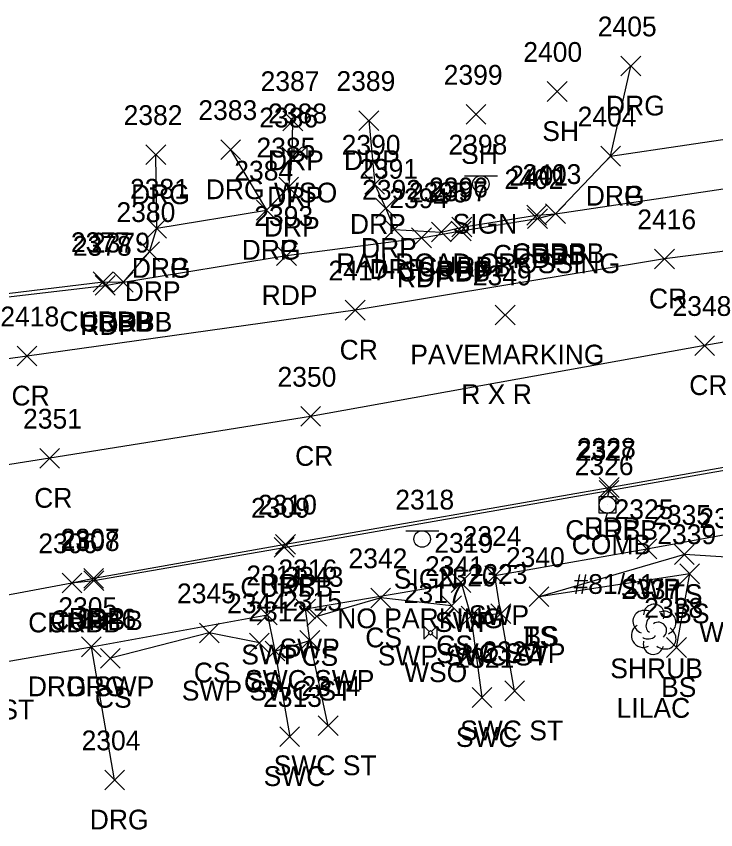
# Model space of a CAD drawing. Extents: x 1769141 to 1770817, y 735471 to 742405.
# Drawn here: x 1770321.5 to 1770392.1, y 741100 to 741182.2 of the extents above; entities that cross this region are included whole.
import ezdxf

# ---------------------------------------------------------------- set-up
doc = ezdxf.new("R2010")
doc.units = 0
for name, color, linetype in [('L_A', 7, 'Continuous'), ('L_C', 7, 'Continuous'), ('L_I', 7, 'Continuous'), ('L_TIC', 7, 'Continuous'), ('LELB', 7, 'Continuous'), ('LSH', 7, 'Continuous'), ('P_A', 7, 'Continuous'), ('P_I', 7, 'Continuous'), ('P_TIC', 7, 'Continuous'), ('PET', 7, 'Continuous'), ('PRC', 7, 'Continuous'), ('R_A', 7, 'Continuous'), ('R_C', 7, 'Continuous'), ('R_I', 7, 'Continuous'), ('R_TIC', 7, 'Continuous'), ('RC', 7, 'Continuous'), ('RDG', 7, 'Continuous'), ('RDP', 7, 'Continuous'), ('RSW', 7, 'Continuous'), ('S_A', 7, 'Continuous'), ('S_C', 7, 'Continuous'), ('S_I', 7, 'Continuous'), ('S_TIC', 7, 'Continuous'), ('SSGN', 7, 'Continuous'), ('U_A', 7, 'Continuous'), ('U_C', 7, 'Continuous'), ('U_I', 7, 'Continuous'), ('UP', 7, 'Continuous'), ('UWV', 7, 'Continuous')]:
    doc.layers.add(name, color=color, linetype=linetype)

msp = doc.modelspace()

# ---------------------------------------------------------------- linework, layer by layer
at = {"layer": 'L_TIC'}
for points in [[(1770375.124, 741173.581), (1770377.124, 741175.581)], [(1770377.124, 741173.581), (1770375.124, 741175.581)], [(1770366.927, 741171.269), (1770368.927, 741173.269)], [(1770368.927, 741171.269), (1770366.927, 741173.269)], [(1770387.976, 741126.777), (1770389.976, 741128.777)], [(1770389.976, 741126.777), (1770387.976, 741128.777)], [(1770388.51, 741124.825), (1770390.51, 741126.825)], [(1770390.51, 741124.825), (1770388.51, 741126.825)], [(1770357.296, 741122.393), (1770359.296, 741124.393)], [(1770359.296, 741122.393), (1770357.296, 741124.393)], [(1770373.288, 741122.515), (1770375.288, 741124.515)], [(1770375.288, 741122.515), (1770373.288, 741124.515)], [(1770373.288, 741122.515), (1770375.288, 741124.515)], [(1770375.288, 741122.515), (1770373.288, 741124.515)], [(1770364.462, 741121.596), (1770366.462, 741123.596)], [(1770366.462, 741121.596), (1770364.462, 741123.596)], [(1770350.84, 741120.521), (1770352.84, 741122.521)], [(1770352.84, 741120.521), (1770350.84, 741122.521)], [(1770339.971, 741118.85), (1770341.971, 741120.85)], [(1770341.971, 741118.85), (1770339.971, 741120.85)], [(1770345.036, 741117.84), (1770347.036, 741119.84)], [(1770347.036, 741117.84), (1770345.036, 741119.84)], [(1770387.178, 741117.38), (1770389.178, 741119.38)], [(1770389.178, 741117.38), (1770387.178, 741119.38)], [(1770329.979, 741116.292), (1770331.979, 741118.292)], [(1770331.979, 741116.292), (1770329.979, 741118.292)]]:
    msp.add_lwpolyline(points, dxfattribs=at)
at = {"layer": 'LELB'}
for points in [[(1770397.71, 741120.075), (1770393.749, 741127.462), (1770388.976, 741127.777), (1770374.288, 741123.515)], [(1770388.178, 741118.38), (1770389.51, 741125.825), (1770374.288, 741123.515)], [(1770365.462, 741122.596), (1770358.296, 741123.393), (1770351.84, 741121.521)], [(1770346.036, 741118.84), (1770340.971, 741119.85), (1770330.979, 741117.292)]]:
    msp.add_lwpolyline(points, dxfattribs=at)
at = {"layer": 'LSH'}
msp.add_line((1770385.857, 741120.272), (1770385.857, 741120.272), dxfattribs=at)
msp.add_line((1770385.857, 741120.272), (1770385.857, 741120.272), dxfattribs=at)
msp.add_arc((1770385.903, 741121.706), 1.047, 335.52715, 180.95627, dxfattribs=at)
for centre, major_axis, ratio, start_param, end_param in [((1770385.065, 741120.939), (1.21, -0.512), 0.895232, 1.570796, 4.712389), ((1770385.648, 741120.73), (-0.208, -0.792), 0.645439, 3.141593, 6.283185), ((1770386.898, 741120.856), (-1.141, -0.483), 0.949671, 1.570796, 4.712389), ((1770386.357, 741120.105), (-0.5, 0.667), 0.989748, 3.141593, 6.283185), ((1770384.773, 741119.564), (0.584, -1.042), 0.959034, 3.141593, 6.283185), ((1770386.857, 741119.439), (-1.09, 0.792), 0.841452, 1.570796, 4.712389), ((1770385.857, 741118.772), (0.265, 1.061), 0.942809, 1.570796, 4.712389), ((1770385.398, 741119.522), (-0.625, -0.083), 0.423636, 0, 3.141593)]:
    msp.add_ellipse(centre, major_axis=major_axis, ratio=ratio, start_param=start_param, end_param=end_param, dxfattribs=at)
at = {"layer": 'P_TIC'}
for points in [[(1770373.133, 741160.731), (1770375.133, 741162.731)], [(1770375.133, 741160.731), (1770373.133, 741162.731)], [(1770374.956, 741161.233), (1770376.956, 741163.233)], [(1770376.956, 741161.233), (1770374.956, 741163.233)], [(1770365.418, 741159.492), (1770367.418, 741161.492)], [(1770367.418, 741159.492), (1770365.418, 741161.492)], [(1770361.422, 741158.793), (1770363.422, 741160.793)], [(1770363.422, 741158.793), (1770361.422, 741160.793)], [(1770347.778, 741156.994), (1770349.778, 741158.994)], [(1770349.778, 741156.994), (1770347.778, 741158.994)], [(1770385.961, 741156.659), (1770387.961, 741158.659)], [(1770387.961, 741156.659), (1770385.961, 741158.659)], [(1770331.291, 741154.308), (1770333.291, 741156.308)], [(1770333.291, 741154.308), (1770331.291, 741156.308)], [(1770329.449, 741153.982), (1770331.449, 741155.982)], [(1770331.449, 741153.982), (1770329.449, 741155.982)], [(1770354.709, 741151.482), (1770356.709, 741153.482)], [(1770356.709, 741151.482), (1770354.709, 741153.482)], [(1770390.031, 741147.9), (1770392.031, 741149.9)], [(1770392.031, 741147.9), (1770390.031, 741149.9)], [(1770321.559, 741146.84), (1770323.559, 741148.84)], [(1770323.559, 741146.84), (1770321.559, 741148.84)], [(1770350.212, 741140.744), (1770352.212, 741142.744)], [(1770352.212, 741140.744), (1770350.212, 741142.744)], [(1770323.852, 741136.505), (1770325.852, 741138.505)], [(1770325.852, 741136.505), (1770323.852, 741138.505)], [(1770380.373, 741133.55), (1770382.373, 741135.55)], [(1770382.373, 741133.55), (1770380.373, 741135.55)], [(1770347.677, 741127.817), (1770349.677, 741129.817)], [(1770349.677, 741127.817), (1770347.677, 741129.817)], [(1770326.096, 741123.908), (1770328.096, 741125.908)], [(1770328.096, 741123.908), (1770326.096, 741125.908)], [(1770328.296, 741124.38), (1770330.296, 741126.38)], [(1770330.296, 741124.38), (1770328.296, 741126.38)]]:
    msp.add_lwpolyline(points, dxfattribs=at)
at = {"layer": 'PET'}
for points in [[(1770275.19, 741166.437), (1770275.977, 741155.599), (1770278.489, 741153.762), (1770283.376, 741153.643), (1770290.834, 741150.945), (1770293.216, 741150.928), (1770301.387, 741151.584), (1770330.449, 741154.982), (1770332.291, 741155.308), (1770348.778, 741157.994), (1770362.422, 741159.793), (1770366.418, 741160.492), (1770374.133, 741161.731), (1770375.956, 741162.233), (1770400.806, 741165.909), (1770403.378, 741166.25), (1770419.604, 741168.76)], [(1770267.402, 741112.794), (1770270.791, 741114.659), (1770274.372, 741115.598), (1770279.067, 741116.593), (1770280.95, 741116.863), (1770285.981, 741117.808), (1770287.654, 741118.086), (1770313.467, 741122.626), (1770315.364, 741122.711), (1770327.096, 741124.908), (1770329.296, 741125.38), (1770348.677, 741128.817), (1770381.373, 741134.55), (1770423.899, 741142.105)]]:
    msp.add_lwpolyline(points, dxfattribs=at)
at = {"layer": 'PRC'}
for points in [[(1770420.662, 741161.961), (1770386.961, 741157.659), (1770355.709, 741152.482), (1770322.559, 741147.84), (1770294.064, 741143.832), (1770270.938, 741141.774), (1770254.424, 741140.369)], [(1770422.288, 741154.401), (1770391.031, 741148.9), (1770351.212, 741141.744), (1770324.852, 741137.505), (1770305.015, 741134.401), (1770279.252, 741130.869), (1770261.05, 741126.482)]]:
    msp.add_lwpolyline(points, dxfattribs=at)
at = {"layer": 'R_TIC'}
for points in [[(1770382.565, 741176.161), (1770384.565, 741178.161)], [(1770384.565, 741176.161), (1770382.565, 741178.161)], [(1770348.417, 741170.625), (1770350.417, 741172.625)], [(1770350.417, 741170.625), (1770348.417, 741172.625)], [(1770356.088, 741170.642), (1770358.088, 741172.642)], [(1770358.088, 741170.642), (1770356.088, 741172.642)], [(1770334.578, 741167.197), (1770336.578, 741169.197)], [(1770336.578, 741167.197), (1770334.578, 741169.197)], [(1770342.128, 741167.701), (1770344.128, 741169.701)], [(1770344.128, 741167.701), (1770342.128, 741169.701)], [(1770348.337, 741166.95), (1770350.337, 741168.95)], [(1770350.337, 741166.95), (1770348.337, 741168.95)], [(1770380.526, 741167.048), (1770382.526, 741169.048)], [(1770382.526, 741167.048), (1770380.526, 741169.048)], [(1770380.526, 741167.048), (1770382.526, 741169.048)], [(1770382.526, 741167.048), (1770380.526, 741169.048)], [(1770348.001, 741163.915), (1770350.001, 741165.915)], [(1770350.001, 741163.915), (1770348.001, 741165.915)], [(1770356.694, 741164.195), (1770358.694, 741166.195)], [(1770358.694, 741164.195), (1770356.694, 741166.195)], [(1770345.758, 741161.585), (1770347.758, 741163.585)], [(1770347.758, 741161.585), (1770345.758, 741163.585)], [(1770345.758, 741161.585), (1770347.758, 741163.585)], [(1770347.758, 741161.585), (1770345.758, 741163.585)], [(1770357.813, 741161.771), (1770359.813, 741163.771)], [(1770359.813, 741161.771), (1770357.813, 741163.771)], [(1770373.048, 741161.08), (1770375.048, 741163.08)], [(1770375.048, 741161.08), (1770373.048, 741163.08)], [(1770374.956, 741161.233), (1770376.956, 741163.233)], [(1770376.956, 741161.233), (1770374.956, 741163.233)], [(1770374.956, 741161.233), (1770376.956, 741163.233)], [(1770376.956, 741161.233), (1770374.956, 741163.233)], [(1770365.492, 741159.882), (1770367.492, 741161.882)], [(1770367.492, 741159.882), (1770365.492, 741161.882)], [(1770334.659, 741159.753), (1770336.659, 741161.753)], [(1770336.659, 741159.753), (1770334.659, 741161.753)], [(1770334.659, 741159.753), (1770336.659, 741161.753)], [(1770336.659, 741159.753), (1770334.659, 741161.753)], [(1770358.676, 741159.647), (1770360.676, 741161.647)], [(1770360.676, 741159.647), (1770358.676, 741161.647)], [(1770363.412, 741159.376), (1770365.412, 741161.376)], [(1770365.412, 741159.376), (1770363.412, 741161.376)], [(1770363.412, 741159.376), (1770365.412, 741161.376)], [(1770365.412, 741159.376), (1770363.412, 741161.376)], [(1770333.942, 741157.391), (1770335.942, 741159.391)], [(1770335.942, 741157.391), (1770333.942, 741159.391)], [(1770329.25, 741154.349), (1770331.25, 741156.349)], [(1770331.25, 741154.349), (1770329.25, 741156.349)], [(1770331.291, 741154.308), (1770333.291, 741156.308)], [(1770333.291, 741154.308), (1770331.291, 741156.308)], [(1770331.291, 741154.308), (1770333.291, 741156.308)], [(1770333.291, 741154.308), (1770331.291, 741156.308)], [(1770380.358, 741133.253), (1770382.358, 741135.253)], [(1770382.358, 741133.253), (1770380.358, 741135.253)], [(1770347.535, 741127.502), (1770349.535, 741129.502)], [(1770349.535, 741127.502), (1770347.535, 741129.502)], [(1770384.176, 741127.353), (1770386.176, 741129.353)], [(1770386.176, 741127.353), (1770384.176, 741129.353)], [(1770368.828, 741124.643), (1770370.828, 741126.643)], [(1770370.828, 741124.643), (1770368.828, 741126.643)], [(1770326.096, 741123.908), (1770328.096, 741125.908)], [(1770328.096, 741123.908), (1770326.096, 741125.908)], [(1770328.309, 741124.136), (1770330.309, 741126.136)], [(1770330.309, 741124.136), (1770328.309, 741126.136)], [(1770365.412, 741123.952), (1770367.412, 741125.952)], [(1770367.412, 741123.952), (1770365.412, 741125.952)], [(1770349.707, 741121.277), (1770351.707, 741123.277)], [(1770351.707, 741121.277), (1770349.707, 741123.277)], [(1770345.845, 741120.665), (1770347.845, 741122.665)], [(1770347.845, 741120.665), (1770345.845, 741122.665)], [(1770366.41, 741120.56), (1770368.41, 741122.56)], [(1770368.41, 741120.56), (1770366.41, 741122.56)], [(1770366.41, 741120.56), (1770368.41, 741122.56)], [(1770368.41, 741120.56), (1770366.41, 741122.56)], [(1770369.433, 741120.809), (1770371.433, 741122.809)], [(1770371.433, 741120.809), (1770369.433, 741122.809)], [(1770369.433, 741120.809), (1770371.433, 741122.809)], [(1770371.433, 741120.809), (1770369.433, 741122.809)], [(1770350.128, 741118.098), (1770352.128, 741120.098)], [(1770352.128, 741118.098), (1770350.128, 741120.098)], [(1770350.128, 741118.098), (1770352.128, 741120.098)], [(1770352.128, 741118.098), (1770350.128, 741120.098)], [(1770328.06, 741117.452), (1770330.06, 741119.452)], [(1770330.06, 741117.452), (1770328.06, 741119.452)], [(1770328.06, 741117.452), (1770330.06, 741119.452)], [(1770330.06, 741117.452), (1770328.06, 741119.452)], [(1770346.607, 741117.02), (1770348.607, 741119.02)], [(1770348.607, 741117.02), (1770346.607, 741119.02)], [(1770346.607, 741117.02), (1770348.607, 741119.02)], [(1770348.607, 741117.02), (1770346.607, 741119.02)], [(1770370.827, 741112.996), (1770372.827, 741114.996)], [(1770372.827, 741112.996), (1770370.827, 741114.996)], [(1770367.527, 741112.327), (1770369.527, 741114.327)], [(1770369.527, 741112.327), (1770367.527, 741114.327)], [(1770351.987, 741109.469), (1770353.987, 741111.469)], [(1770353.987, 741109.469), (1770351.987, 741111.469)], [(1770348.103, 741108.373), (1770350.103, 741110.373)], [(1770350.103, 741108.373), (1770348.103, 741110.373)], [(1770330.409, 741103.986), (1770332.409, 741105.986)], [(1770332.409, 741103.986), (1770330.409, 741105.986)]]:
    msp.add_lwpolyline(points, dxfattribs=at)
at = {"layer": 'RC'}
for points in [[(1770364.412, 741160.376), (1770366.492, 741160.882), (1770374.048, 741162.08), (1770375.956, 741162.233)], [(1770290.834, 741150.945), (1770293.288, 741151.247), (1770301.388, 741151.851), (1770330.25, 741155.349), (1770332.291, 741155.308)], [(1770327.096, 741124.908), (1770329.309, 741125.136), (1770348.535, 741128.502), (1770381.358, 741134.253), (1770424.024, 741141.766)]]:
    msp.add_lwpolyline(points, dxfattribs=at)
at = {"layer": 'RDG'}
for points in [[(1770381.526, 741168.048), (1770383.565, 741177.161)], [(1770343.128, 741168.701), (1770346.758, 741162.585)], [(1770335.659, 741160.753), (1770335.578, 741168.197)], [(1770331.409, 741104.986), (1770329.06, 741118.452)]]:
    msp.add_lwpolyline(points, dxfattribs=at)
at = {"layer": 'RDP'}
for points in [[(1770332.291, 741155.308), (1770334.942, 741158.391), (1770335.659, 741160.753), (1770346.758, 741162.585), (1770349.001, 741164.915), (1770349.337, 741167.95), (1770349.417, 741171.625)], [(1770357.088, 741171.642), (1770357.694, 741165.195), (1770358.813, 741162.771), (1770359.676, 741160.647), (1770364.412, 741160.376)], [(1770375.956, 741162.233), (1770381.526, 741168.048), (1770396.926, 741170.338), (1770398.792, 741167.297), (1770400.806, 741165.909)]]:
    msp.add_lwpolyline(points, dxfattribs=at)
at = {"layer": 'RSW'}
for points in [[(1770293.745, 741112.25), (1770315.627, 741116.109), (1770329.06, 741118.452), (1770346.845, 741121.665), (1770347.607, 741118.02), (1770351.128, 741119.098), (1770350.707, 741122.277), (1770366.412, 741124.952), (1770367.41, 741121.56), (1770370.433, 741121.809), (1770369.828, 741125.643), (1770385.176, 741128.353), (1770423.885, 741135.428)], [(1770367.41, 741121.56), (1770368.527, 741113.327)], [(1770371.827, 741113.996), (1770370.433, 741121.809)], [(1770352.987, 741110.469), (1770351.128, 741119.098)], [(1770347.607, 741118.02), (1770349.103, 741109.373)]]:
    msp.add_lwpolyline(points, dxfattribs=at)
at = {"layer": 'S_TIC'}
for points in [[(1770369.866, 741150.989), (1770371.866, 741152.989)], [(1770371.866, 741150.989), (1770369.866, 741152.989)]]:
    msp.add_lwpolyline(points, dxfattribs=at)
at = {"layer": 'SSGN'}
for p, q in [((1770366.769, 741166.068), (1770370.102, 741166.068)), ((1770368.416, 741165.235), (1770368.416, 741165.235)), ((1770360.831, 741130.179), (1770364.164, 741130.179)), ((1770362.478, 741129.346), (1770362.478, 741129.346))]:
    msp.add_line(p, q, dxfattribs=at)
for centre in [(1770368.416, 741165.235), (1770362.478, 741129.346)]:
    msp.add_circle(centre, 0.833, dxfattribs=at)
at = {"layer": 'UP'}
for p, q in [((1770381.455, 741134.464), (1770381.205, 741133.631)), ((1770380.372, 741131.964), (1770380.372, 741133.631)), ((1770380.372, 741133.631), (1770382.038, 741133.631)), ((1770382.038, 741133.631), (1770382.038, 741131.964)), ((1770381.205, 741132.797), (1770381.205, 741132.797)), ((1770382.038, 741131.964), (1770380.372, 741131.964)), ((1770380.955, 741131.131), (1770381.205, 741131.964))]:
    msp.add_line(p, q, dxfattribs=at)
msp.add_circle((1770381.205, 741132.797), 0.833, dxfattribs=at)
at = {"layer": 'UWV'}
for p, q in [((1770349.517, 741169.035), (1770350.066, 741168.486)), ((1770350.851, 741169.035), (1770350.302, 741168.486)), ((1770350.066, 741168.251), (1770349.517, 741167.702)), ((1770350.302, 741168.251), (1770350.851, 741167.702)), ((1770362.654, 741120.544), (1770363.203, 741119.995)), ((1770363.987, 741120.544), (1770363.439, 741119.995)), ((1770363.203, 741119.759), (1770362.654, 741119.211)), ((1770363.439, 741119.759), (1770363.987, 741119.211))]:
    msp.add_line(p, q, dxfattribs=at)
for points in [[(1770349.517, 741169.035), (1770349.517, 741167.702)], [(1770350.851, 741167.702), (1770350.851, 741169.035)], [(1770362.654, 741120.544), (1770362.654, 741119.211)], [(1770363.987, 741119.211), (1770363.987, 741120.544)]]:
    msp.add_lwpolyline(points, dxfattribs=at)
for points in [[(1770350.42, 741168.368), (1770350.184, 741168.604), (1770349.948, 741168.368), (1770350.184, 741168.133)], [(1770363.556, 741119.877), (1770363.321, 741120.113), (1770363.085, 741119.877), (1770363.321, 741119.642)]]:
    msp.add_lwpolyline(points, close=True, dxfattribs=at)

# ---------------------------------------------------------------- texts
at = {"layer": 'L_A'}
for s, p in [('SH', (1770374.613, 741169.581)), ('SH', (1770366.415, 741167.269)), ('TS', (1770387.386, 741122.777)), ('BS', (1770387.951, 741120.825)), ('CS', (1770356.737, 741118.393)), ('TS', (1770372.697, 741118.515)), ('BS', (1770372.729, 741118.515)), ('CS', (1770363.903, 741117.596)), ('CS', (1770350.281, 741116.521)), ('CS', (1770339.412, 741114.85)), ('SHRUB', (1770381.487, 741115.272)), ('CS', (1770344.477, 741113.84)), ('BS', (1770386.619, 741113.38)), ('CS', (1770329.42, 741112.292))]:
    msp.add_text(s, height=2, dxfattribs=at).set_placement(p)
at = {"layer": 'L_C'}
msp.add_text('LILAC', height=2, dxfattribs=at).set_placement((1770382.132, 741111.272))
at = {"layer": 'L_I'}
for s, p in [('2400', (1770372.699, 741177.581)), ('2399', (1770364.659, 741175.269)), ('2335', (1770385.717, 741130.777)), ('2334', (1770390.489, 741130.462)), ('2339', (1770386.242, 741128.825)), ('2342', (1770355.036, 741126.393)), ('2340', (1770370.942, 741126.515)), ('2340', (1770370.942, 741126.515)), ('2341', (1770362.769, 741125.596)), ('2343', (1770348.58, 741124.521)), ('2345', (1770337.711, 741122.85)), ('2337', (1770382.597, 741123.272)), ('2344', (1770342.776, 741121.84)), ('2338', (1770384.919, 741121.38)), ('2346', (1770327.664, 741120.292))]:
    msp.add_text(s, height=2, dxfattribs=at).set_placement(p)
at = {"layer": 'P_A'}
for s, p in [('RDP', (1770371.621, 741156.731)), ('RDP', (1770373.444, 741157.233)), ('RDP', (1770363.906, 741155.492)), ('RDP', (1770359.91, 741154.793)), ('RDP', (1770346.266, 741152.994)), ('CR', (1770385.394, 741152.659)), ('RDP', (1770327.937, 741149.982)), ('RDP', (1770329.779, 741150.308)), ('CR', (1770354.143, 741147.482)), ('CR', (1770389.464, 741143.9)), ('CR', (1770320.992, 741142.84)), ('CR', (1770349.645, 741136.744)), ('CR', (1770323.285, 741132.505)), ('RDP', (1770378.861, 741129.55)), ('RDP', (1770346.165, 741123.817)), ('RDP', (1770326.784, 741120.38)), ('RDP', (1770324.584, 741119.908))]:
    msp.add_text(s, height=2, dxfattribs=at).set_placement(p)
at = {"layer": 'P_I'}
for s, p in [('2402', (1770370.794, 741164.731)), ('2403', (1770372.617, 741165.233)), ('2397', (1770363.158, 741163.492)), ('2394', (1770359.163, 741162.793)), ('2393', (1770345.518, 741160.994)), ('2416', (1770384.213, 741160.659)), ('2379', (1770329.023, 741158.308)), ('2378', (1770327.189, 741157.982)), ('2417', (1770353.017, 741155.482)), ('2348', (1770387.771, 741151.9)), ('2418', (1770319.866, 741150.84)), ('2350', (1770347.866, 741144.744)), ('2351', (1770322.16, 741140.505)), ('2328', (1770378.113, 741137.55)), ('2310', (1770345.898, 741131.817)), ('2306', (1770323.702, 741127.908)), ('2307', (1770325.958, 741128.38))]:
    msp.add_text(s, height=2, dxfattribs=at).set_placement(p)
at = {"layer": 'R_A'}
for s, p in [('DRG', (1770381.053, 741172.161)), ('DRP', (1770346.905, 741166.625)), ('DRP', (1770354.576, 741166.642)), ('DRG', (1770333.066, 741163.197)), ('DRG', (1770340.616, 741163.701)), ('DRG', (1770379.014, 741163.048)), ('DRP', (1770346.825, 741162.95)), ('DRP', (1770379.014, 741163.048)), ('DRP', (1770346.489, 741159.915)), ('DRP', (1770355.182, 741160.195)), ('DRG', (1770344.246, 741157.585)), ('DRP', (1770344.246, 741157.585)), ('DRP', (1770356.301, 741157.771)), ('CURBB', (1770369.631, 741157.08)), ('CURBB', (1770371.539, 741157.233)), ('DRP', (1770373.444, 741157.233)), ('DRG', (1770333.147, 741155.753)), ('DRP', (1770333.147, 741155.753)), ('CURBB', (1770362.075, 741155.882)), ('DRP', (1770357.164, 741155.647)), ('CURBB', (1770359.994, 741155.376)), ('DRP', (1770361.9, 741155.376)), ('DRP', (1770332.43, 741153.391)), ('CURBB', (1770325.832, 741150.349)), ('CURBB', (1770327.874, 741150.308)), ('DRP', (1770329.779, 741150.308)), ('CURBB', (1770376.941, 741129.253)), ('CURBB', (1770344.117, 741123.502)), ('SWP', (1770382.539, 741123.353)), ('SWP', (1770367.19, 741120.643)), ('CURBB', (1770322.679, 741119.908)), ('CURBB', (1770324.892, 741120.136)), ('SWP', (1770363.775, 741119.952)), ('SWP', (1770348.069, 741117.277)), ('SWP', (1770344.207, 741116.665)), ('SWP SWC ST', (1770358, 741116.56)), ('SWP SWC ST', (1770358, 741116.56)), ('SWC SWP', (1770363.89, 741116.809)), ('SWC SWP', (1770363.89, 741116.809)), ('SWC SWP', (1770344.585, 741114.098)), ('SWC SWP', (1770344.585, 741114.098)), ('DRG SWP', (1770322.642, 741113.452)), ('DRG', (1770326.548, 741113.452)), ('SWP SWC ST', (1770338.197, 741113.02)), ('SWP SWC ST', (1770338.197, 741113.02)), ('SWP DRG ST', (1770306.344, 741111.109)), ('SWC ST', (1770366.323, 741108.996)), ('SWC', (1770365.89, 741108.327)), ('SWC ST', (1770347.483, 741105.469)), ('SWC', (1770346.465, 741104.373)), ('DRG', (1770328.897, 741099.986))]:
    msp.add_text(s, height=2, dxfattribs=at).set_placement(p)
at = {"layer": 'R_C'}
msp.add_text('WOODEN', height=2, dxfattribs=at).set_placement((1770390.467, 741118.944))
at = {"layer": 'R_I'}
for s, p in [('2405', (1770380.226, 741180.161)), ('2387', (1770346.158, 741174.625)), ('2389', (1770353.821, 741174.642)), ('2383', (1770339.868, 741171.701)), ('2382', (1770332.318, 741171.197)), ('2386', (1770346.022, 741170.95)), ('2404', (1770378.187, 741171.048)), ('2404', (1770378.187, 741171.048)), ('2390', (1770354.348, 741168.195)), ('2385', (1770345.741, 741167.915)), ('2384', (1770343.499, 741165.585)), ('2384', (1770343.499, 741165.585)), ('2391', (1770356.12, 741165.771)), ('2401', (1770371.277, 741165.08)), ('2403', (1770372.617, 741165.233)), ('2403', (1770372.617, 741165.233)), ('2396', (1770363.177, 741163.882)), ('2381', (1770332.966, 741163.753)), ('2381', (1770332.966, 741163.753)), ('2392', (1770356.416, 741163.647)), ('2395', (1770361.152, 741163.376)), ('2395', (1770361.152, 741163.376)), ('2380', (1770331.596, 741161.391)), ('2377', (1770326.99, 741158.349)), ('2379', (1770329.023, 741158.308)), ('2379', (1770329.023, 741158.308)), ('2327', (1770378.099, 741137.253)), ('2309', (1770345.189, 741131.502)), ('2325', (1770381.917, 741131.353)), ('2324', (1770366.568, 741128.643)), ('2306', (1770323.702, 741127.908)), ('2308', (1770325.971, 741128.136)), ('2319', (1770363.712, 741127.952)), ('2316', (1770347.959, 741125.277)), ('2311', (1770344.719, 741124.665)), ('2320', (1770364.063, 741124.56)), ('2320', (1770364.063, 741124.56)), ('2323', (1770367.173, 741124.809)), ('2323', (1770367.173, 741124.809)), ('2315', (1770348.436, 741122.098)), ('2315', (1770348.436, 741122.098)), ('2305', (1770325.721, 741121.452)), ('2305', (1770325.721, 741121.452)), ('2312', (1770344.914, 741121.02)), ('2312', (1770344.914, 741121.02)), ('2322', (1770368.567, 741116.996)), ('2321', (1770365.835, 741116.327)), ('2314', (1770350.295, 741113.469)), ('2313', (1770346.41, 741112.373)), ('2304', (1770328.071, 741107.986))]:
    msp.add_text(s, height=2, dxfattribs=at).set_placement(p)
at = {"layer": 'S_A'}
for s, p in [('SIGN', (1770365.554, 741160.215)), ('PAVEMARKING', (1770361.283, 741146.989)), ('SIGN', (1770359.616, 741124.326))]:
    msp.add_text(s, height=2, dxfattribs=at).set_placement(p)
at = {"layer": 'S_C'}
for s, p in [('RAILROAD CROSSING', (1770353.806, 741156.215)), ('R X R', (1770366.433, 741142.989)), ('NO PARKING', (1770353.899, 741120.326))]:
    msp.add_text(s, height=2, dxfattribs=at).set_placement(p)
at = {"layer": 'S_I'}
for s, p in [('2398', (1770365.136, 741168.215)), ('2349', (1770367.598, 741154.989)), ('2318', (1770359.766, 741132.326))]:
    msp.add_text(s, height=2, dxfattribs=at).set_placement(p)
at = {"layer": 'U_A'}
for s, p in [('WSO', (1770347.515, 741163.368)), ('COMB', (1770377.591, 741127.797)), ('WSO', (1770360.652, 741114.877))]:
    msp.add_text(s, height=2, dxfattribs=at).set_placement(p)
at = {"layer": 'U_C'}
msp.add_text('#81/11', height=2, dxfattribs=at).set_placement((1770377.772, 741123.797))
at = {"layer": 'U_I'}
for s, p in [('2388', (1770346.924, 741171.368)), ('2326', (1770377.89, 741135.797)), ('2317', (1770360.628, 741122.877))]:
    msp.add_text(s, height=2, dxfattribs=at).set_placement(p)

doc.saveas('drawing.dxf')
